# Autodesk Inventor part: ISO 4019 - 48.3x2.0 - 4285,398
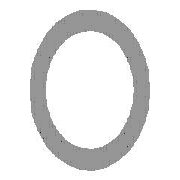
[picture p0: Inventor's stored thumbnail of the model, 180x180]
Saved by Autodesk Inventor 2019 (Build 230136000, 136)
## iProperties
_CCFamilyMember: 14
_CCFamilyDisplayName: ISO 4019 (Profils creux circulaires - Formés à froid) - Aciers de construction - Coupes creuses profilées formées à froid, soudées — ISO 4019 (Profils creux cir
_FrameMemberDoc: Frame Member File
_Version: 15.0.0
_GetPNFromCC: 1
Created: 2018-01
Part Number: ISO 4019 - 48.3x2.0 - 4285,398
Material: Acier, doux
Description: Aciers de construction - Coupes creuses profilées formées à froid, soudées
Document SubType Name: Modeling
Standard: ISO
Designer: Fabian Perrée
Standard Revision: Second edition 2001-09-01
Standards Organization: ISO
Language: fr-FR
Size Designation: 48.3x2.0
Categories: <MemberInstance><Categories><Category DisplayName="Profilés" InternalName="089c4875-fa83-4c05-b084-43b9cc11f5ed" Mnemonic="GRDR"><CategoryParameter DisplayName=
Stock Number: 48.3x2.0
Density: 7.85 g/cm^3
Appearance: Semi-poli
Mass: 9786.37 g
Surface Area: 12472.5 cm^2
Volume: 1246.67 cm^3
IsCustomPart: 1
G_W: 48,300 mm
G_H: 48,300 mm
G_L: 4285,398 mm
Author: Fabian Perrée
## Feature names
1. Corps
## Parameters: d0 = 48.3 mm, d1 = 2 mm, G_H = 48.3 mm, G_T = 2 mm, G_L = 4285.39816 mm, G_OFFSET_START = 0, G_OFFSET_END = 0, d4 = 0, d5 = 4285.39816 mm, B_L = 4285.39816 mm, d6 = 90 deg, d7 = 4285.39816 mm, MAS = 0.228 mm, d8 = 0, d9 = 0
